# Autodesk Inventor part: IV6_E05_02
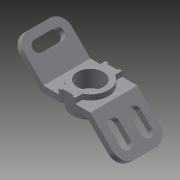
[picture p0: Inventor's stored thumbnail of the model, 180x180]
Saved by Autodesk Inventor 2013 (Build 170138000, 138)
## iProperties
Shininess: 64.0
Length Units: 11269
Angle Units: 11279
Time Units: 11290
Mass Units: 11283
Length Display Precision: 3
Angle Display Precision: 2
Created: 2002-08
Part Number: IV6_E05_02
Document SubType Name: Modeling
Designer: t_munrn
Density: 1 g/cm^3
Material: Generic
Density: 0.0
Volumn: 0.0
Area: 0.0
PropertySet Name: Model Information
Control State: 0
Master: False
Checked Out: False
Author: t_munrn
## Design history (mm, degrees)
sketch "Sketch1"
  geometry: L1 (-45, 0)-(45, 0); L2 (0, 0)-(0, -12); L3 (-45, 0)-(-98.033, 53.033); L4 (-98.033, 53.033)-(-106.518, 44.548); L5 (-106.518, 44.548)-(-49.971, -12); L6 (-49.971, -12)-(40.029, -12); L7 (40.029, -12)-(96.619, -68.589); L8 (96.619, -68.589)-(105.104, -60.104); L9 (105.104, -60.104)-(45, 0); 1 further point
  constraints: 18 end point, 4 perpendicular, 3 parallel, 2 equal length, 1 coincident, 1 horizontal, 1 midpoint, 1 point on line
  dimensions: "d0" = 90 distance of L1.start L1.end; "d1" = 85 distance of L8.end L1.end; "d2" = 12 distance of L3.end L4.end; "d3" = 75 distance of L1.start L3.end; "d4" = 45 deg angle of L5 L6
extrude "Extrusion1" new body sketch "Sketch1" stored distance "d5" = 90; taper "d6" = 0 deg
sketch "Sketch2"
  geometry: C1 r 35 at (45, 45); 1 further point
  constraints: 1 centre point, 1 coincident
  dimensions: "d7" = 70 diameter of C1
extrude "Extrusion2" join sketch "Sketch2" distance "d8" = 10; taper "d9" = 0 deg
sketch "Sketch6"
  geometry: C1 r 35 at (49.971, -45) reference
extrude "Extrusion3" join sketch "Sketch6" distance "d26" = 20; taper "d27" = 0 deg
sketch "Sketch3"
  geometry: L1 (-45, 0)-(45, 0) reference; L2 (-35, 10)-(35, 10) reference; L3 (0, 10)-(0, 0); L4 (-16, 10)-(-16, 0); L5 (16, 10)-(16, 0)
  constraints: 6 end point, 4 point on line, 2 midpoint, 2 perpendicular
  dimensions: "d10" = 16 distance between parallel lines of L4 L3; "d11" = 16 distance between parallel lines of L5 L3
extrude "Extrusion4" join sketch "Sketch3" stored distance "d12" = 13; taper "d13" = 0 deg
sketch "Sketch4"
  geometry: A1 r 35 centre (45, 45) between (29, 76.129) and (29, 13.871) reference
hole "Hole1" sketch "Sketch4" at (45, 45) diameter "d14" = 25; stored, may be unused: countersink angle "d18" = 82 deg, drill point angle "d20" = 118 deg; dims "d15" = 6, "d16" = 50, "d17" = 32, "d19" = 8
sketch "Sketch5"
  geometry: L1 (29, 90)-(61, 90) reference; L2 (29, 76.129)-(29, 90) reference; L3 (35, 90)-(35, 87); L4 (35, 87)-(55, 87); L5 (55, 87)-(55, 90); L6 (45, 87)-(45, 90); L7 (61, 76.129)-(61, 90) reference
  constraints: 8 end point, 2 midpoint, 2 parallel, 2 perpendicular, 2 point on line
  dimensions: "d22" = 3 distance of L4.end L5.end; "d28" = 6 distance between parallel lines of L7 L5
extrude "Extrusion5" cut sketch "Sketch5" stored distance "d23" = 13; taper "d24" = 0 deg
fillet "Fillet1" dims "d25" = 25
sketch "Sketch7"
  geometry: L1 (60, 65)-(60, 25); L2 (40, 65)-(40, 25); A1 r 25 centre (50, 25) between (50, 0) and (75, 25) reference; A2 r 25 centre (50, 65) between (75, 65) and (50, 90) reference; A3 r 10 centre (50, 65) between (60, 65) and (40, 65); A4 r 10 centre (50, 25) between (60, 25) and (40, 25)
  constraints: 4 end point, 4 point on circle, 4 tangent, 2 centre point, 2 coincident, 1 equal radius
  dimensions: "d29" = 20 diameter of A4
extrude "Extrusion6" cut sketch "Sketch7" stored distance "d30" = 20; taper "d31" = 0 deg
sketch "Sketch8"
  geometry: L1 (-60, 75)-(-30, 75); L2 (-60, 55)-(-30, 55); A1 r 25 centre (-60, 65) between (-60, 90) and (-85, 65) reference; A2 r 10 centre (-60, 65) between (-60, 75) and (-60, 55); A3 r 10 centre (-30, 65) between (-30, 75) and (-30, 55)
  constraints: 4 end point, 4 point on circle, 4 tangent, 2 centre point, 1 coincident, 1 equal radius, 1 horizontal alignment
  dimensions: "d32" = 20 diameter of A2; "d33" = 30 distance of L1.start L1.end
extrude "Extrusion7" cut sketch "Sketch8" stored distance "d34" = 20; taper "d35" = 0 deg
mirror "Mirror1"
body "Solid1"
